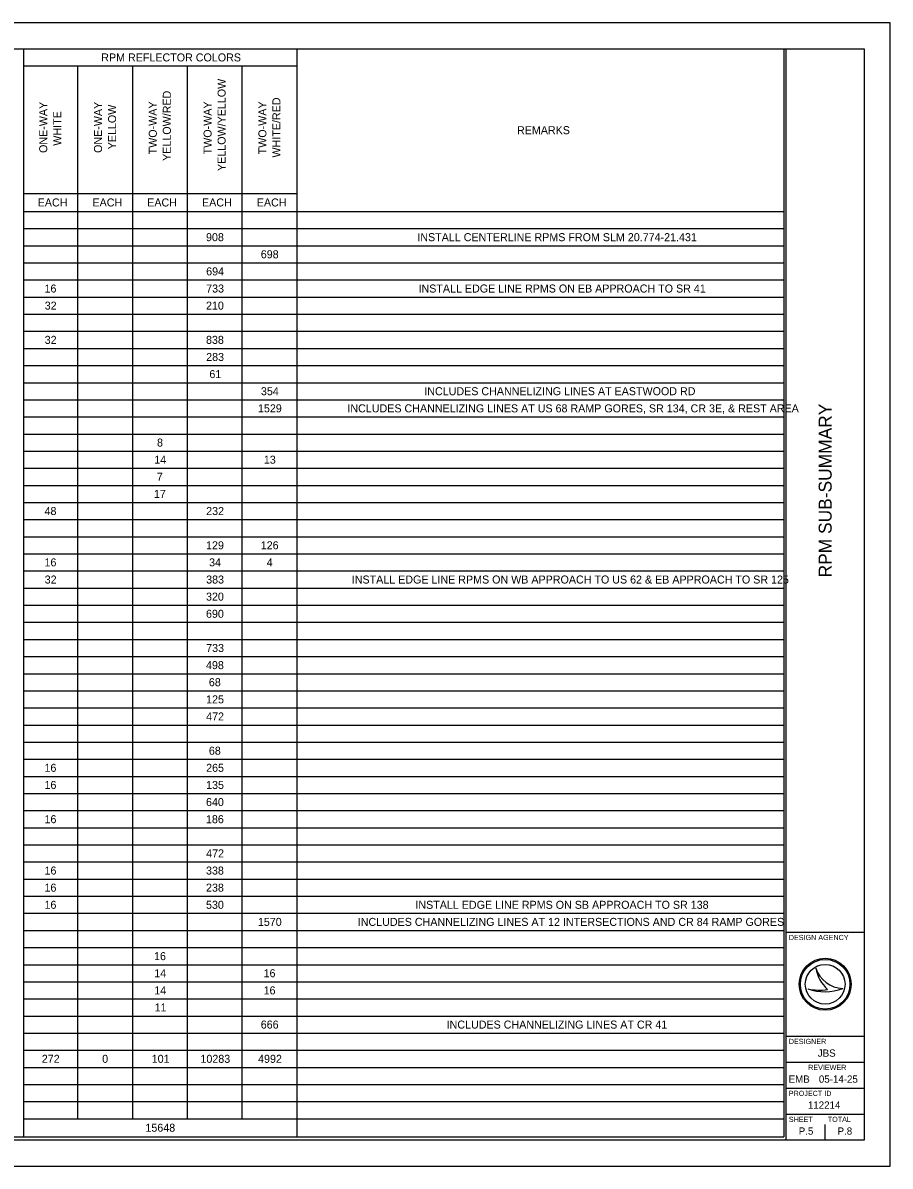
# Model space of a CAD drawing. Extents: x 0 to 34, y 0 to 22.
# Drawn here: x 17.31 to 34, y 0 to 22 of the extents above; entities that cross this region are included whole.
import ezdxf

# ---------------------------------------------------------------- set-up
doc = ezdxf.new("R2010")
doc.units = 0
for name, color, linetype in [('Default', 7, 'Continuous'), ('SH_Border', 7, 'Continuous'), ('SH_Cut_Line', 7, 'Continuous'), ('SH_Data', 7, 'Continuous')]:
    doc.layers.add(name, color=color, linetype=linetype)

msp = doc.modelspace()

# ---------------------------------------------------------------- linework, layer by layer
at = {"layer": 'Default'}
for p, q in [((15.193, 21.5), (17.323, 21.5)), ((17.301, 21.5), (31.954, 21.5)), ((17.323, 21.5), (17.323, 0.566)), ((22.582, 21.5), (22.582, 0.566)), ((31.954, 21.5), (31.954, 0.566)), ((17.323, 21.171), (22.582, 21.171)), ((18.366, 21.171), (18.366, 0.912)), ((19.42, 21.171), (19.42, 0.912)), ((20.474, 21.171), (20.474, 0.912)), ((21.528, 21.171), (21.528, 0.912)), ((17.323, 18.716), (22.582, 18.716)), ((17.323, 18.371), (31.954, 18.371)), ((17.323, 18.041), (31.954, 18.041)), ((17.323, 17.712), (31.954, 17.712)), ((17.323, 17.382), (31.954, 17.382)), ((17.323, 17.053), (31.954, 17.053)), ((17.323, 16.724), (31.954, 16.724)), ((17.323, 16.394), (31.954, 16.394)), ((17.323, 16.065), (31.954, 16.065)), ((17.323, 15.735), (31.954, 15.735)), ((17.323, 15.406), (31.954, 15.406)), ((17.323, 15.076), (31.954, 15.076)), ((17.323, 14.747), (31.954, 14.747)), ((17.323, 14.418), (31.954, 14.418)), ((17.323, 14.088), (31.954, 14.088)), ((17.323, 13.759), (31.954, 13.759)), ((17.323, 13.429), (31.954, 13.429)), ((17.323, 13.1), (31.954, 13.1)), ((17.323, 12.771), (31.954, 12.771)), ((17.323, 12.441), (31.954, 12.441)), ((17.323, 12.112), (31.954, 12.112)), ((17.323, 11.782), (31.954, 11.782)), ((17.323, 11.453), (31.954, 11.453)), ((17.323, 11.124), (31.954, 11.124)), ((17.323, 10.794), (31.954, 10.794)), ((17.323, 10.465), (31.954, 10.465)), ((17.323, 10.135), (31.954, 10.135)), ((17.323, 9.806), (31.954, 9.806)), ((17.323, 9.476), (31.954, 9.476)), ((17.323, 9.147), (31.954, 9.147)), ((17.323, 8.818), (31.954, 8.818)), ((17.323, 8.488), (31.954, 8.488)), ((17.323, 8.159), (31.954, 8.159)), ((17.323, 7.829), (31.954, 7.829)), ((17.323, 7.5), (31.954, 7.5)), ((17.323, 7.171), (31.954, 7.171)), ((17.323, 6.841), (31.954, 6.841)), ((17.323, 6.512), (31.954, 6.512)), ((17.323, 6.182), (31.954, 6.182)), ((17.323, 5.853), (31.954, 5.853)), ((17.323, 5.524), (31.954, 5.524)), ((17.323, 5.194), (31.954, 5.194)), ((17.323, 4.865), (31.954, 4.865)), ((17.323, 4.535), (31.954, 4.535)), ((17.323, 4.206), (31.954, 4.206)), ((17.323, 3.876), (31.954, 3.876)), ((17.323, 3.547), (31.954, 3.547)), ((17.323, 3.218), (31.954, 3.218)), ((17.323, 2.888), (31.954, 2.888)), ((17.323, 2.559), (31.954, 2.559)), ((17.323, 2.229), (31.954, 2.229)), ((17.323, 1.9), (31.954, 1.9)), ((17.323, 1.571), (31.954, 1.571)), ((17.323, 1.241), (31.954, 1.241)), ((17.323, 0.912), (31.954, 0.912)), ((15.193, 0.566), (17.323, 0.566)), ((17.301, 0.566), (31.954, 0.566))]:
    msp.add_line(p, q, dxfattribs=at)
at = {"layer": 'SH_Border'}
for p, q in [((32, 0.5), (32, 21.5)), ((32, 4.5), (33.5, 4.5)), ((32, 2.5), (33.5, 2.5)), ((32, 2), (33.5, 2)), ((32, 1.5), (33.5, 1.5)), ((32, 1), (33.5, 1))]:
    msp.add_line(p, q, dxfattribs=at)
msp.add_lwpolyline([(1.5, 21.5), (33.5, 21.5), (33.5, 0.5), (1.5, 0.5)], close=True, dxfattribs=at)
at = {"layer": 'SH_Cut_Line'}
msp.add_lwpolyline([(0, 0), (34, 0), (34, 22), (0, 22)], close=True, dxfattribs=at)
at = {"layer": 'SH_Data'}
for p, q in [((32.567, 3.81), (32.567, 3.81)), ((32.417, 3.41), (32.417, 3.41)), ((32.75, 3.5), (32.75, 3.5)), ((33.087, 3.419), (33.087, 3.419)), ((32.375, 0.675), (32.375, 0.675)), ((32.75, 0.5), (32.75, 0.8))]:
    msp.add_line(p, q, dxfattribs=at)
for radius in [0.5, 0.477, 0.477, 0.382]:
    msp.add_circle((32.75, 3.5), radius, dxfattribs=at)
for centre, radius, start, end in [((33.116, 3.998), 0.58, 198.9257, 198.9319), ((33.347, 3.97), 0.796, 191.6379, 191.6421), ((33.116, 3.998), 0.58, 198.9319, 267.1657), ((33.347, 3.97), 0.796, 191.6421, 226.0947), ((32.739, 4.37), 1.013, 251.4576, 290.0832), ((32.648, 4.654), 1.266, 259.4964, 259.4995), ((32.739, 4.37), 1.013, 251.4527, 251.4576), ((32.648, 4.654), 1.266, 259.4995, 276.6672)]:
    msp.add_arc(centre, radius, start, end, dxfattribs=at)

# ---------------------------------------------------------------- texts
at = {"layer": 'Default'}
for s, p in [('RPM REFLECTOR COLORS', (18.82, 21.258)), ('REMARKS', (26.82, 19.858)), ('EACH', (17.597, 18.467)), ('EACH', (18.651, 18.467)), ('EACH', (19.705, 18.467)), ('EACH', (20.759, 18.467)), ('EACH', (21.813, 18.467)), ('908', (20.836, 17.799)), ('INSTALL CENTERLINE RPMS FROM SLM 20.774-21.431', (24.902, 17.799)), ('698', (21.89, 17.47)), ('694', (20.839, 17.141)), ('16', (17.728, 16.811)), ('733', (20.839, 16.811)), ('INSTALL EDGE LINE RPMS ON EB APPROACH TO SR 41', (24.925, 16.811)), ('32', (17.732, 16.482)), ('210', (20.836, 16.482)), ('32', (17.732, 15.823)), ('838', (20.836, 15.823)), ('283', (20.839, 15.494)), ('61', (20.901, 15.164)), ('354', (21.893, 14.835)), ('INCLUDES CHANNELIZING LINES AT EASTWOOD RD', (25.036, 14.835)), ('1529', (21.836, 14.505)), ('INCLUDES CHANNELIZING LINES AT US 68 RAMP GORES, SR 134, CR 3E, & REST AREA', (23.557, 14.505)), ('8', (19.893, 13.847)), ('14', (19.84, 13.517)), ('13', (21.949, 13.517)), ('7', (19.889, 13.188)), ('17', (19.833, 12.858)), ('48', (17.729, 12.529)), ('232', (20.839, 12.529)), ('129', (20.837, 11.87)), ('126', (21.889, 11.87)), ('16', (17.728, 11.541)), ('34', (20.895, 11.541)), ('4', (22.004, 11.541)), ('32', (17.732, 11.211)), ('383', (20.839, 11.211)), ('INSTALL EDGE LINE RPMS ON WB APPROACH TO US 62 & EB APPROACH TO SR 125', (23.641, 11.211)), ('320', (20.836, 10.882)), ('690', (20.836, 10.552)), ('733', (20.839, 9.894)), ('498', (20.836, 9.564)), ('68', (20.891, 9.235)), ('125', (20.838, 8.905)), ('472', (20.839, 8.576)), ('68', (20.891, 7.917)), ('16', (17.728, 7.588)), ('265', (20.838, 7.588)), ('16', (17.728, 7.258)), ('135', (20.838, 7.258)), ('640', (20.836, 6.929)), ('16', (17.728, 6.599)), ('186', (20.835, 6.599)), ('472', (20.839, 5.941)), ('16', (17.728, 5.611)), ('338', (20.836, 5.611)), ('16', (17.728, 5.282)), ('238', (20.836, 5.282)), ('16', (17.728, 4.952)), ('530', (20.836, 4.952)), ('INSTALL EDGE LINE RPMS ON SB APPROACH TO SR 138', (24.865, 4.952)), ('1570', (21.834, 4.623)), ('INCLUDES CHANNELIZING LINES AT 12 INTERSECTIONS AND CR 84 RAMP GORES', (23.756, 4.623)), ('16', (19.836, 3.964)), ('14', (19.84, 3.635)), ('16', (21.944, 3.635)), ('14', (19.84, 3.305)), ('16', (21.944, 3.305)), ('11', (19.846, 2.976)), ('666', (21.889, 2.647)), ('INCLUDES CHANNELIZING LINES AT CR 41', (25.466, 2.647)), ('272', (17.676, 1.988)), ('0', (18.838, 1.988)), ('101', (19.791, 1.988)), ('10283', (20.729, 1.988)), ('4992', (21.838, 1.988)), ('15648', (19.67, 0.662))]:
    msp.add_text(s, height=0.154, dxfattribs=at).set_placement(p)
for s, p in [('YELLOW/YELLOW', (21.213, 19.15)), ('YELLOW/RED', (20.159, 19.344)), ('ONE-WAY ', (17.781, 19.497)), ('ONE-WAY', (18.835, 19.497)), ('TWO-WAY', (19.889, 19.47)), ('TWO-WAY', (20.943, 19.47)), ('TWO-WAY', (21.998, 19.47)), ('WHITE/RED', (22.267, 19.409)), ('WHITE', (18.051, 19.636)), ('YELLOW', (19.105, 19.567))]:
    msp.add_text(s, height=0.154, rotation=90, dxfattribs=at).set_placement(p)
at = {"layer": 'SH_Data'}
msp.add_text('RPM SUB-SUMMARY', height=0.25, rotation=90, dxfattribs=at).set_placement((32.875, 11.329))
for s, height, p in [('DESIGN AGENCY', 0.1, (32.05, 4.35)), ('DESIGNER', 0.1, (32.05, 2.35)), ('JBS', 0.14, (32.608, 2.105)), ('REVIEWER', 0.1, (32.422, 1.85)), ('EMB', 0.14, (32.047, 1.605)), ('05-14-25', 0.14, (32.629, 1.605)), ('PROJECT ID', 0.1, (32.05, 1.35)), ('112214', 0.14, (32.418, 1.105)), ('SHEET', 0.1, (32.05, 0.85)), ('TOTAL', 0.1, (32.8, 0.85)), ('P.5', 0.14, (32.241, 0.605)), ('P.8', 0.14, (32.989, 0.605))]:
    msp.add_text(s, height=height, dxfattribs=at).set_placement(p)

doc.saveas('drawing.dxf')
